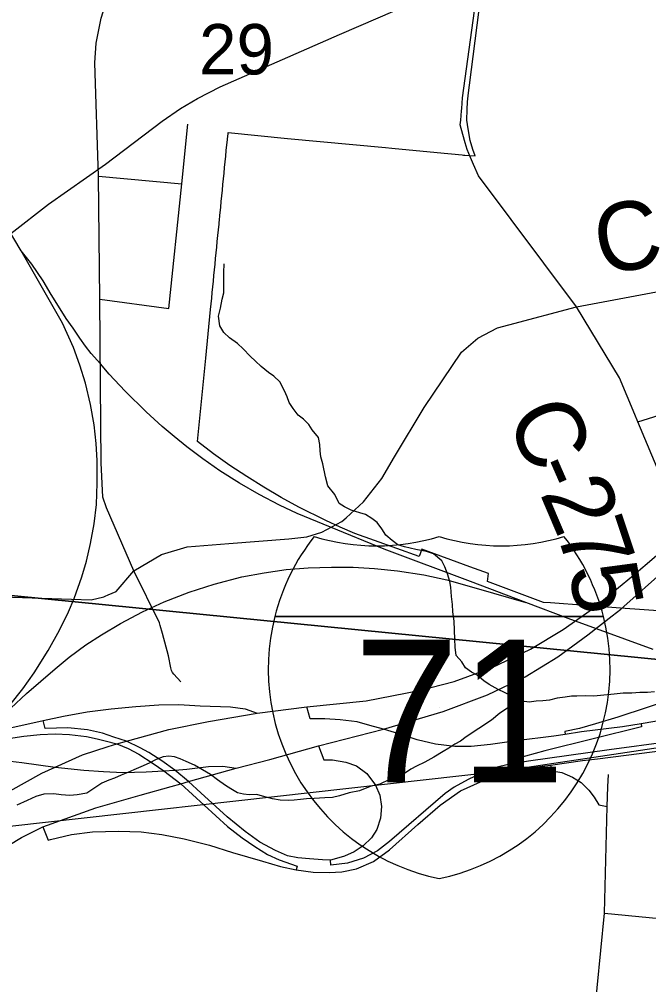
# Model space of a CAD drawing. Extents: x 0 to 34, y -3.9 to 26.2.
# Drawn here: x 4.053 to 4.576, y 14.888 to 15.69 of the extents above; entities that cross this region are included whole.
import ezdxf

# ---------------------------------------------------------------- set-up
doc = ezdxf.new("R2010")
doc.units = 0
for name, color, linetype in [('GM_X_City_Street', 7, 'Continuous'), ('GM_X_County_Road', 7, 'Continuous'), ('GM_X_County_Road_Text', 7, 'Continuous'), ('GM_X_Interchange_Ramps', 7, 'Continuous'), ('GM_X_Interstate_Location', 7, 'Continuous'), ('GM_X_Interstate_Route', 7, 'Continuous'), ('GM_X_Interstate_Shield', 7, 'Continuous'), ('GM_X_Minor_River', 7, 'Continuous'), ('GM_X_Rail_Line', 7, 'Continuous'), ('GM_X_Section', 7, 'Continuous'), ('GM_X_Section_Text', 7, 'Continuous'), ('GM_X_State_Route', 7, 'Continuous'), ('GM_X_Township_Road', 7, 'Continuous')]:
    doc.layers.add(name, color=color, linetype=linetype)

msp = doc.modelspace()

# ---------------------------------------------------------------- linework, layer by layer
at = {"layer": 'GM_X_City_Street'}
for p, q in [((4.11912, 15.55975), (4.18823, 15.5534)), ((4.12009, 15.45757), (4.17751, 15.44991))]:
    msp.add_line(p, q, dxfattribs=at)
for points in [[(4.17751, 15.44991), (4.18823, 15.5534), (4.19337, 15.60301)], [(4.18745, 15.13978), (4.18172, 15.14615), (4.18071, 15.14736), (4.1799, 15.14905), (4.1793, 15.1512), (4.17724, 15.16126), (4.17241, 15.17994), (4.17046, 15.18655), (4.16971, 15.1887), (4.14851, 15.23179)], [(4.53966, 14.9475), (4.67975, 14.93379), (4.74846, 14.92122)]]:
    msp.add_lwpolyline(points, dxfattribs=at)
at = {"layer": 'GM_X_County_Road'}
msp.add_line((4.46014, 15.43631), (4.51631, 15.45112), dxfattribs=at)
for points in [[(4.12075, 15.38753), (4.12009, 15.45757), (4.11912, 15.55975), (4.11597, 15.65378), (4.11703, 15.6701), (4.12123, 15.69091), (4.14693, 15.77212), (4.16604, 15.83251), (4.17295, 15.85435), (4.17474, 15.86874), (4.17696, 15.88542), (4.1775, 15.89435), (4.18154, 15.96108), (4.18528, 16.02288), (4.18661, 16.04481), (4.19304, 16.15099), (4.19645, 16.2074)], [(4.42178, 15.62478), (4.43501, 15.72138), (4.43305, 15.73516), (4.42984, 15.7576), (4.42194, 15.81286), (4.42046, 15.82322)], [(4.42085, 15.61407), (4.42101, 15.61602), (4.42178, 15.62478)], [(4.42204, 15.5944), (4.41983, 15.6024), (4.42017, 15.60629), (4.42085, 15.61407)], [(4.42836, 15.57518), (4.42551, 15.58177), (4.42397, 15.58739), (4.42204, 15.5944)], [(4.62531, 15.18359), (4.62476, 15.19324), (4.62273, 15.20471), (4.61981, 15.22094), (4.60918, 15.24962), (4.60366, 15.26247), (4.5928, 15.29493), (4.56748, 15.35553), (4.5648, 15.36163), (4.5521, 15.39228), (4.51631, 15.45112), (4.43496, 15.55992), (4.43081, 15.56954), (4.42836, 15.57518)], [(4.51631, 15.45112), (4.62728, 15.47206), (4.66649, 15.47801), (4.68249, 15.48043), (4.70909, 15.48179), (4.73981, 15.48041), (4.80045, 15.47499)], [(4.32489, 15.276), (4.33942, 15.28908), (4.3546, 15.30853), (4.3652, 15.32655), (4.3899, 15.36746), (4.42077, 15.41357), (4.43428, 15.42507), (4.45077, 15.43385), (4.46014, 15.43631)], [(4.14851, 15.23179), (4.1256, 15.28431), (4.12273, 15.29311), (4.12137, 15.32163), (4.12076, 15.38653), (4.12075, 15.38753)], [(4.14851, 15.23179), (4.17154, 15.24538), (4.19292, 15.25179), (4.22753, 15.2545), (4.27734, 15.25843), (4.29217, 15.26003), (4.30477, 15.26395), (4.32127, 15.27273), (4.32489, 15.276)], [(4.12717, 15.21184), (4.13375, 15.21462), (4.14851, 15.23179)], [(4.01652, 15.21123), (4.01752, 15.21119), (4.04748, 15.20991), (4.11312, 15.20782), (4.12342, 15.21027), (4.12458, 15.21076), (4.12717, 15.21184)], [(4.52233, 14.76557), (4.52701, 14.8133), (4.53354, 14.88538), (4.53966, 14.9475), (4.54189, 15.03617), (4.54239, 15.0525), (4.54313, 15.06264)]]:
    msp.add_lwpolyline(points, dxfattribs=at)
at = {"layer": 'GM_X_Interchange_Ramps'}
msp.add_line((4.53394, 15.07579), (4.59226, 15.08309), dxfattribs=at)
for points in [[(4.61987, 15.19606), (4.55307, 15.20093), (4.49471, 15.20518), (4.4891, 15.20559), (4.44255, 15.22294), (4.44321, 15.22961), (4.42781, 15.23524), (4.38779, 15.24989), (4.38551, 15.24371), (4.34839, 15.25719), (4.33227, 15.26302), (4.3201, 15.26816), (4.30804, 15.27359), (4.28564, 15.28476), (4.27095, 15.29279), (4.25651, 15.30125), (4.24231, 15.31013), (4.22839, 15.31943), (4.21474, 15.32913), (4.20139, 15.33922), (4.20823, 15.40855), (4.21224, 15.44904), (4.21271, 15.45376), (4.21318, 15.45847), (4.21362, 15.46319), (4.21408, 15.46791), (4.21458, 15.47261), (4.21505, 15.47732), (4.21552, 15.48204), (4.21598, 15.48675), (4.21645, 15.49146), (4.21692, 15.49618), (4.21739, 15.50089), (4.21785, 15.5056), (4.21832, 15.51032), (4.21879, 15.51503), (4.21926, 15.51974), (4.2197, 15.52447), (4.21984, 15.52564), (4.22001, 15.52729), (4.22019, 15.52918), (4.22066, 15.53389), (4.22113, 15.5386), (4.2216, 15.54331), (4.22207, 15.54802), (4.22253, 15.55274), (4.223, 15.55745), (4.22347, 15.56216), (4.22394, 15.56687), (4.22441, 15.57158), (4.22488, 15.57629), (4.22534, 15.58101), (4.22581, 15.58572), (4.22624, 15.59005), (4.22628, 15.59043), (4.22675, 15.59514), (4.2268, 15.59571), (4.22684, 15.59601), (4.27614, 15.59116), (4.35756, 15.58346), (4.36306, 15.58294), (4.40066, 15.57938), (4.42133, 15.57743), (4.42257, 15.57731), (4.42373, 15.5772), (4.43212, 15.57669), (4.43015, 15.58188), (4.42818, 15.58938), (4.42627, 15.59918), (4.42535, 15.60634), (4.42542, 15.61503), (4.42581, 15.6214), (4.42653, 15.62884), (4.42745, 15.63528), (4.43699, 15.7092)], [(4.62402, 15.14105), (4.61494, 15.14193), (4.61295, 15.13693), (4.60847, 15.13211), (4.60418, 15.1292), (4.5986, 15.12605), (4.55089, 15.1102), (4.53209, 15.10466), (4.51885, 15.10094), (4.50672, 15.09848), (4.50712, 15.09593)], [(4.59287, 15.10861), (4.57016, 15.10482), (4.55455, 15.10222), (4.52067, 15.09804), (4.50712, 15.09593), (4.49746, 15.09443), (4.46637, 15.09065), (4.44497, 15.08761), (4.42876, 15.08594), (4.41517, 15.08591), (4.39909, 15.08774), (4.38399, 15.09161), (4.37141, 15.09552), (4.35604, 15.1002), (4.34467, 15.10343), (4.33413, 15.10637), (4.31996, 15.10815), (4.3072, 15.10887), (4.29514, 15.1088), (4.29236, 15.11885)], [(4.30191, 15.08641), (4.30635, 15.0749), (4.31348, 15.07499), (4.32455, 15.07302), (4.33355, 15.06994), (4.3421, 15.06347), (4.34945, 15.05393), (4.35296, 15.0456), (4.35427, 15.03617), (4.3534, 15.02641), (4.35033, 15.01687), (4.34605, 15.01007), (4.33914, 15.00338), (4.33157, 14.99855), (4.32348, 14.99482), (4.31503, 14.99236), (4.31198, 14.99141), (4.30536, 14.99175), (4.29462, 14.99252), (4.28475, 14.9934), (4.27608, 14.99515), (4.26632, 14.99943), (4.25316, 15.00656), (4.24099, 15.01522), (4.22597, 15.02761), (4.20403, 15.04746), (4.19381, 15.05681), (4.18241, 15.0663), (4.17179, 15.07411), (4.16104, 15.08091), (4.15381, 15.08486), (4.14243, 15.09041), (4.13196, 15.0938), (4.12244, 15.09692), (4.10994, 15.09966), (4.09371, 15.10142), (4.07463, 15.10098), (4.07303, 15.1076)], [(4.62241, 15.10184), (4.61407, 15.10223), (4.61197, 15.09929), (4.60936, 15.09668), (4.60717, 15.09474), (4.60439, 15.09348), (4.60144, 15.09222), (4.59791, 15.09087), (4.59328, 15.08986), (4.54353, 15.08304), (4.47656, 15.07362), (4.46112, 15.07117), (4.44791, 15.06809), (4.43644, 15.06319), (4.42633, 15.05855), (4.41476, 15.05221), (4.40724, 15.04697), (4.36096, 15.00711), (4.35098, 14.99921), (4.33947, 14.99307), (4.3262, 14.98901), (4.31227, 14.98737), (4.31198, 14.99141)], [(4.57016, 15.10482), (4.57058, 15.10224), (4.49001, 15.0822), (4.47411, 15.078), (4.46042, 15.0742), (4.46112, 15.07117)], [(4.0038, 15.08578), (4.02906, 15.08985), (4.04415, 15.09257), (4.05701, 15.09455), (4.07062, 15.09578), (4.08299, 15.09652), (4.09486, 15.09603), (4.10921, 15.0943), (4.11811, 15.09232), (4.12454, 15.09059), (4.13428, 15.08802), (4.14384, 15.0844), (4.15274, 15.07946), (4.16461, 15.07179), (4.17353, 15.06573), (4.18742, 15.05503), (4.22645, 15.0196), (4.23857, 15.00995), (4.24896, 15.00278), (4.2596, 14.99635), (4.26925, 14.99165), (4.28433, 14.98658), (4.28349, 14.98351)], [(4.28349, 14.98351), (4.2975, 14.98161), (4.31086, 14.98114), (4.32135, 14.98185), (4.33351, 14.98424), (4.34782, 14.99052), (4.36097, 15.00008), (4.3845, 15.02111), (4.40303, 15.03715), (4.41994, 15.04914), (4.43656, 15.05665), (4.45216, 15.06244), (4.46625, 15.06612), (4.47879, 15.06848), (4.49487, 15.0705), (4.5213, 15.0742), (4.53394, 15.07579)], [(4.49487, 15.0705), (4.49555, 15.06579), (4.50432, 15.06432), (4.5131, 15.06042), (4.52042, 15.05604), (4.52676, 15.04969), (4.53115, 15.04384), (4.53505, 15.03749), (4.54189, 15.03617)], [(4.07278, 15.01917), (4.07717, 15.00806), (4.07919, 15.00872), (4.09672, 15.01287), (4.11409, 15.01498), (4.13569, 15.0157), (4.15462, 15.01491), (4.17173, 15.01273), (4.19038, 15.0092), (4.2113, 15.004), (4.23055, 14.99788), (4.25536, 14.99056), (4.27032, 14.98627), (4.28349, 14.98351)]]:
    msp.add_lwpolyline(points, dxfattribs=at)
at = {"layer": 'GM_X_Interstate_Route'}
for points in [[(4.29236, 15.11885), (4.34167, 15.12396), (4.38575, 15.13252), (4.41482, 15.13986), (4.44585, 15.15116), (4.47831, 15.16673), (4.50529, 15.18307), (4.52985, 15.2004), (4.5622, 15.22683), (4.60366, 15.26247), (4.62082, 15.27679), (4.6911, 15.33743), (4.74946, 15.38685)], [(4.5462, 15.19458), (4.55325, 15.20005), (4.59128, 15.23376)], [(4.23347, 15.06801), (4.26154, 15.07525), (4.30191, 15.08641), (4.35604, 15.1002), (4.40564, 15.11495), (4.44249, 15.12877), (4.47363, 15.1439), (4.50083, 15.16035), (4.52583, 15.17877), (4.5462, 15.19458)], [(3.96088, 14.97739), (3.98011, 14.99741), (3.99985, 15.01583), (4.02222, 15.0336), (4.04569, 15.04917), (4.07211, 15.06376), (4.08308, 15.0688), (4.10567, 15.07889), (4.12717, 15.08591), (4.13428, 15.08802), (4.14243, 15.09041), (4.17752, 15.09998), (4.21058, 15.10671), (4.25096, 15.11373), (4.29236, 15.11885)], [(4.17942, 15.05281), (4.18742, 15.05503), (4.19381, 15.05681), (4.23347, 15.06801)], [(3.93469, 14.90688), (3.94856, 14.92435), (3.96457, 14.94212), (3.98058, 14.95659), (4.00471, 14.97699), (4.02598, 14.99278), (4.05516, 15.01033), (4.07278, 15.01917), (4.11679, 15.03511), (4.15363, 15.04564), (4.17942, 15.05281)]]:
    msp.add_lwpolyline(points, dxfattribs=at)
at = {"layer": 'GM_X_Interstate_Shield'}
for p, q in [((4.26561, 15.19382), (4.53887, 15.19382)), ((4.53887, 15.19382), (4.26561, 15.19382)), ((4.53887, 15.19382), (4.26561, 15.19382))]:
    msp.add_line(p, q, dxfattribs=at)
for centre, start, end in [((4.43775, 15.15028), 141.66896, 165.80665), ((4.35035, 15.43021), 253.00908, 286.99093), ((4.45413, 15.43021), 253.00908, 286.99093), ((4.36673, 15.15028), 14.19335, 38.33104), ((4.43775, 15.15028), 165.80665, 258.46304), ((4.36673, 15.15028), 281.53696, 14.19335)]:
    msp.add_arc(centre, 0.17756, start, end, dxfattribs=at)
at = {"layer": 'GM_X_Minor_River'}
for points in [[(4.58122, 15.13143), (4.5755, 15.13091), (4.56904, 15.1308), (4.56256, 15.13031), (4.55534, 15.13023), (4.5477, 15.1294), (4.53626, 15.12836), (4.53092, 15.12782), (4.52409, 15.1281), (4.51685, 15.12764), (4.5123, 15.12783), (4.50694, 15.12691), (4.50045, 15.12604), (4.49393, 15.12441), (4.48858, 15.12388), (4.48288, 15.12373), (4.47714, 15.12283), (4.47109, 15.12346), (4.4662, 15.1248), (4.46178, 15.12841), (4.45134, 15.1334), (4.4439, 15.13751), (4.43945, 15.14036), (4.43394, 15.14515), (4.4291, 15.14763), (4.4243, 15.15125), (4.42108, 15.15633), (4.41634, 15.16146), (4.41547, 15.16834), (4.41536, 15.17519), (4.4148, 15.19003), (4.41358, 15.19769), (4.41344, 15.20378), (4.41258, 15.21066), (4.41211, 15.21828), (4.41116, 15.22288), (4.40913, 15.22942), (4.40708, 15.23521), (4.40462, 15.24025), (4.39762, 15.24587), (4.39162, 15.24802), (4.38294, 15.24952), (4.37353, 15.25181), (4.3679, 15.25356), (4.3631, 15.25718), (4.35796, 15.26158), (4.35474, 15.26665), (4.35077, 15.27214), (4.34634, 15.27536), (4.34115, 15.27862), (4.33626, 15.27996), (4.32912, 15.28216), (4.32354, 15.28505), (4.31909, 15.2879), (4.31558, 15.29526), (4.30978, 15.30235), (4.3078, 15.31003), (4.30556, 15.32077), (4.30389, 15.32654), (4.30333, 15.3315), (4.30315, 15.33683), (4.30186, 15.34259), (4.29679, 15.34888), (4.29393, 15.35356), (4.28954, 15.35792), (4.28511, 15.36115), (4.28077, 15.36665), (4.27755, 15.37172), (4.27583, 15.37635), (4.27375, 15.38138), (4.26986, 15.38877), (4.26472, 15.39354), (4.26029, 15.39677), (4.2544, 15.40157), (4.24963, 15.40595), (4.24524, 15.41032), (4.2394, 15.41626), (4.23463, 15.42064), (4.22798, 15.42547), (4.22321, 15.42985), (4.22001, 15.43531), (4.2188, 15.44334), (4.22059, 15.45011), (4.22202, 15.45765), (4.22337, 15.46292), (4.2234, 15.47318), (4.22327, 15.47964), (4.22355, 15.48685)], [(4.46896, 15.12404), (4.46529, 15.12104), (4.45986, 15.11822), (4.45284, 15.11357), (4.44577, 15.10778), (4.4247, 15.09384), (4.42, 15.09023), (4.41534, 15.08776), (4.41027, 15.08455), (4.4056, 15.0817), (4.39782, 15.07708), (4.39043, 15.07283), (4.38346, 15.0697), (4.37881, 15.06723), (4.37256, 15.06293), (4.36098, 15.05847), (4.35285, 15.05462), (4.34479, 15.05267), (4.33592, 15.04924), (4.32748, 15.04731), (4.31941, 15.04499), (4.31366, 15.0437), (4.30718, 15.04321), (4.29842, 15.04282), (4.29194, 15.04233), (4.28698, 15.04177), (4.28164, 15.04123), (4.27707, 15.04104), (4.27024, 15.04132), (4.26382, 15.04235), (4.25555, 15.0446), (4.25066, 15.04594), (4.2442, 15.04583), (4.23966, 15.0464), (4.23476, 15.04736), (4.22919, 15.05063), (4.22474, 15.05348), (4.21809, 15.05832), (4.21218, 15.06274), (4.20549, 15.06644), (4.19881, 15.07052), (4.19208, 15.07346), (4.18685, 15.07558), (4.18235, 15.07728), (4.17744, 15.07787), (4.17285, 15.0773), (4.16707, 15.07526), (4.16125, 15.07208), (4.15428, 15.06894), (4.14849, 15.06653), (4.14347, 15.06445), (4.13805, 15.06202), (4.13226, 15.0596), (4.12763, 15.05789), (4.12183, 15.05547), (4.1152, 15.05118), (4.10935, 15.04724), (4.10131, 15.04567), (4.09521, 15.04517), (4.08801, 15.04585), (4.08196, 15.04648), (4.0736, 15.04645), (4.06706, 15.04444), (4.0597, 15.04094), (4.05119, 15.03711)]]:
    msp.add_lwpolyline(points, dxfattribs=at)
at = {"layer": 'GM_X_Rail_Line'}
for points in [[(4.07763, 15.53643), (4.12499, 15.56976), (4.17193, 15.60549), (4.18724, 15.61598), (4.20128, 15.62435), (4.22014, 15.63385), (4.31947, 15.67741), (4.38179, 15.70418)], [(4.58015, 15.16657), (4.50943, 15.1924), (4.47438, 15.20548), (4.4283, 15.22292), (4.35655, 15.24986), (4.31193, 15.26811), (4.28437, 15.27959), (4.26947, 15.28643), (4.25261, 15.29523), (4.23624, 15.30475), (4.22, 15.31494), (4.20585, 15.32505), (4.19263, 15.33494), (4.18194, 15.34358), (4.17193, 15.35181), (4.15879, 15.36399), (4.14116, 15.38102), (4.12783, 15.39534), (4.12084, 15.40381), (4.11294, 15.4125), (4.10833, 15.41862), (4.10358, 15.42526), (4.09791, 15.43354), (4.09223, 15.44157), (4.08573, 15.45185), (4.0797, 15.46151), (4.07301, 15.47292), (4.06363, 15.48663), (4.05494, 15.4976), (4.02565, 15.54627)], [(4.00812, 15.48966), (4.01597, 15.49402), (4.03017, 15.50169), (4.04615, 15.5121), (4.07763, 15.53643)], [(4.02913, 15.10324), (4.0453, 15.1204), (4.05608, 15.13373), (4.06572, 15.14705), (4.07735, 15.16563), (4.0867, 15.18265), (4.09422, 15.19782), (4.0989, 15.20902), (4.10514, 15.22675), (4.10911, 15.23993), (4.11251, 15.25468), (4.11549, 15.27084), (4.11733, 15.28701), (4.11804, 15.30474), (4.1179, 15.32345), (4.11719, 15.33777), (4.11549, 15.35323), (4.11251, 15.36996), (4.10826, 15.38783), (4.10358, 15.40272), (4.09833, 15.41732), (4.08912, 15.4376), (4.05494, 15.4976)], [(4.04615, 15.11784), (4.0592, 15.1299), (4.08302, 15.15046), (4.09465, 15.1601), (4.10868, 15.17031), (4.12145, 15.17882), (4.13747, 15.18818), (4.15576, 15.19768), (4.17377, 15.20618), (4.19433, 15.21427), (4.21532, 15.22093), (4.23815, 15.22675), (4.25686, 15.23015), (4.27516, 15.23284), (4.29331, 15.2344), (4.31287, 15.23497), (4.33088, 15.23483), (4.34861, 15.23384), (4.36775, 15.23185), (4.38959, 15.22859), (4.40859, 15.22433), (4.43312, 15.21739), (4.47438, 15.20548)], [(4.66554, 15.12584), (4.64486, 15.10127), (4.63072, 15.09184), (4.45322, 15.06511), (3.91898, 15.00528)]]:
    msp.add_lwpolyline(points, dxfattribs=at)
at = {"layer": 'GM_X_Section'}
for points in [[(3.78177, 16.24865), (4.78471, 16.15816), (4.69633, 15.14722), (3.68487, 15.24697)], [(3.68487, 15.24697), (4.69633, 15.14722), (4.59807, 14.13459), (3.58071, 14.24166)]]:
    msp.add_lwpolyline(points, close=True, dxfattribs=at)
at = {"layer": 'GM_X_State_Route'}
for points in [[(4.07303, 15.1076), (4.08989, 15.11124), (4.10965, 15.11467), (4.12953, 15.11718), (4.15013, 15.11916), (4.16922, 15.1206), (4.18596, 15.12076), (4.2035, 15.11978), (4.22892, 15.11896), (4.24101, 15.1171), (4.25096, 15.11373)], [(3.36863, 15.00864), (3.39539, 15.00447), (3.4228, 15.00228), (3.45373, 15.00316), (3.47566, 15.00579), (3.49321, 15.00952), (3.51536, 15.01566), (3.5408, 15.02531), (3.57119, 15.03928), (3.60815, 15.05784), (3.63796, 15.06939), (3.6653, 15.07814), (3.69105, 15.08314), (3.71275, 15.08526), (3.73602, 15.08569), (3.82199, 15.08153), (3.84469, 15.08087), (3.86853, 15.08094), (3.91305, 15.08193), (3.94966, 15.0849), (3.99307, 15.09022), (4.02455, 15.09671), (4.04712, 15.10184), (4.07303, 15.1076)], [(4.00487, 15.07576), (4.03148, 15.07547), (4.05523, 15.07275), (4.08308, 15.0688), (4.10677, 15.06628), (4.12321, 15.06523), (4.13944, 15.06435), (4.15863, 15.06479), (4.17353, 15.06573), (4.18241, 15.0663), (4.19251, 15.0671), (4.21061, 15.06929), (4.22257, 15.06973), (4.23347, 15.06801)]]:
    msp.add_lwpolyline(points, dxfattribs=at)
at = {"layer": 'GM_X_Township_Road'}
msp.add_line((4.56748, 15.35553), (4.6743, 15.39018), dxfattribs=at)

# ---------------------------------------------------------------- texts
at = {"layer": 'GM_X_County_Road_Text'}
for s, rotation, p in [('C', 10.67635, (4.53691, 15.47702)), ('C', 293.78873, (4.45753, 15.36024)), ('-', 293.64905, (4.47634, 15.31757)), ('2', 293.10465, (4.48564, 15.29633)), ('7', 288.46705, (4.49894, 15.26527)), ('5', 280.81242, (4.50952, 15.23401))]:
    msp.add_text(s, height=0.05682, rotation=rotation, dxfattribs=at).set_placement(p)
at = {"layer": 'GM_X_Interstate_Location'}
for s in ['-', '.', ',']:
    msp.add_text(s, height=0.000189, dxfattribs=at).set_placement((4.40221, 15.11826))
msp.add_text('71', height=0.000189, rotation=0.00001, dxfattribs=at).set_placement((4.36352, 15.07906))
at = {"layer": 'GM_X_Interstate_Shield'}
msp.add_text('71', height=0.118371, dxfattribs=at).set_placement((4.33101, 15.05621))
at = {"layer": 'GM_X_Section_Text'}
msp.add_text('29', height=0.041856, rotation=0.00001, dxfattribs=at).set_placement((4.20269, 15.64425))

doc.saveas('drawing.dxf')
